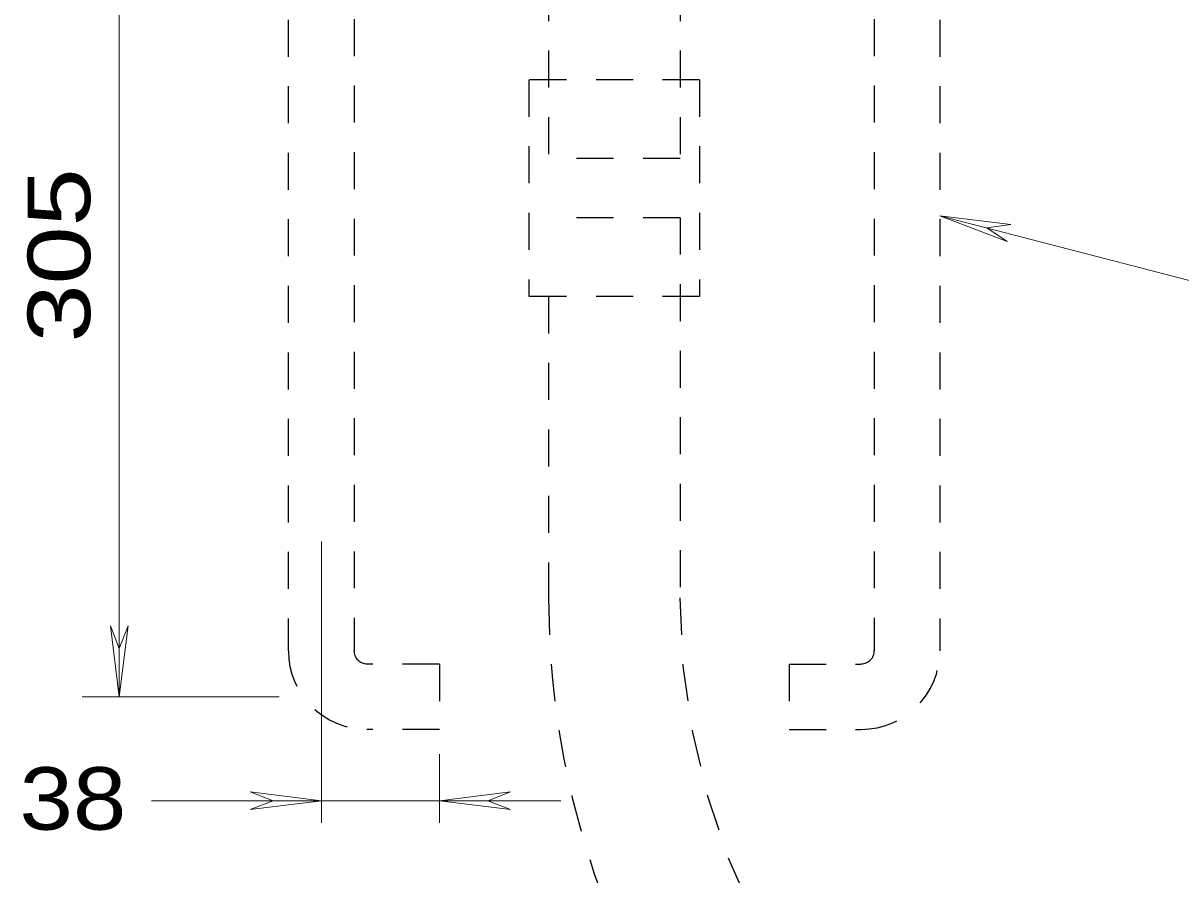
# Model space of a CAD drawing. Extents: x 312583 to 312854, y 144419 to 144597.
# Drawn here: x 312706.7 to 312720.79, y 144494.68 to 144505.05 of the extents above; entities that cross this region are included whole.
import ezdxf

# ---------------------------------------------------------------- set-up
doc = ezdxf.new("R2010")
doc.units = 0
doc.header["$LTSCALE"] = 0.3
doc.linetypes.add('SHORT_DASHED', pattern=[2.7, 1.5, -1.2])
doc.layers.add('1', color=7, linetype='Continuous', lineweight=25)
doc.layers.add('2', color=7, linetype='Continuous', lineweight=13)

msp = doc.modelspace()

# ---------------------------------------------------------------- linework, layer by layer
at = {"layer": '1', "linetype": 'SHORT_DASHED'}
for p, q in [((312713.0932, 144507.9535), (312713.0932, 144503.3995)), ((312714.6955, 144507.9535), (312714.6955, 144503.3995)), ((312709.9269, 144505.8989), (312709.9269, 144497.4042)), ((312710.7319, 144505.9065), (312710.7319, 144497.4042)), ((312717.0569, 144505.9065), (312717.0569, 144497.4042)), ((312717.8542, 144505.8989), (312717.8542, 144497.4042)), ((312714.9332, 144504.3579), (312712.8555, 144504.3579)), ((312712.8555, 144504.3579), (312712.8555, 144501.7205)), ((312714.9332, 144504.3579), (312714.9332, 144501.7205)), ((312714.6955, 144503.3995), (312713.0932, 144503.3995)), ((312714.6955, 144502.6789), (312713.0932, 144502.6789)), ((312714.6955, 144502.6789), (312714.6955, 144498.0482)), ((312714.9332, 144501.7205), (312712.8555, 144501.7205)), ((312713.0932, 144501.7205), (312713.0932, 144498.0482)), ((312711.7669, 144497.2432), (312710.8852, 144497.2432)), ((312711.7669, 144497.2432), (312711.7669, 144496.4459)), ((312716.0219, 144497.2432), (312716.0219, 144496.4459)), ((312716.0219, 144497.2432), (312716.8959, 144497.2432)), ((312711.7669, 144496.4459), (312710.8852, 144496.4459)), ((312716.0219, 144496.4459), (312716.8959, 144496.4459))]:
    msp.add_line(p, q, dxfattribs=at)
at = {"layer": '1', "lineweight": 13}
for p, q in [((312710.3332, 144498.7382), (312710.3332, 144495.3112)), ((312711.7669, 144496.1469), (312711.7669, 144495.3112)), ((312708.2632, 144495.5795), (312713.2465, 144495.5795))]:
    msp.add_line(p, q, dxfattribs=at)
at = {"layer": '1', "linetype": 'SHORT_DASHED'}
for centre, radius, start, end in [((312723.4767, 144498.0511), 10.3816, 180, 264.70346), ((312723.4767, 144498.0511), 8.785, 180, 263.73732), ((312710.8881, 144497.4071), 0.9583, 180, 270), ((312710.8881, 144497.4071), 0.16, 180, 270), ((312716.8987, 144497.4071), 0.9583, 270, 0), ((312716.8987, 144497.4071), 0.16, 270, 0)]:
    msp.add_arc(centre, radius, start, end, dxfattribs=at)
at = {"layer": '2'}
for p, q in [((312707.8722, 144496.8445), (312707.8722, 144507.3785)), ((312717.8542, 144502.7019), (312718.6745, 144502.3875)), ((312717.8542, 144502.7019), (312718.7205, 144502.5945)), ((312718.7205, 144502.5945), (312718.4292, 144502.5562)), ((312718.6745, 144502.3875), (312718.4292, 144502.5562)), ((312707.7649, 144497.7109), (312707.8722, 144497.4349)), ((312707.8722, 144496.8445), (312707.7649, 144497.7109)), ((312707.9795, 144497.7109), (312707.8722, 144497.4349)), ((312707.8722, 144496.8445), (312707.9795, 144497.7109)), ((312709.8195, 144496.8445), (312707.4199, 144496.8445)), ((312709.4669, 144495.6869), (312709.7429, 144495.5795)), ((312710.3332, 144495.5795), (312709.4669, 144495.6869)), ((312711.7669, 144495.5795), (312712.6332, 144495.6869)), ((312712.6332, 144495.6869), (312712.3572, 144495.5795)), ((312709.4669, 144495.4722), (312709.7429, 144495.5795)), ((312710.3332, 144495.5795), (312709.4669, 144495.4722)), ((312711.7669, 144495.5795), (312712.6332, 144495.4722)), ((312712.6332, 144495.4722), (312712.3572, 144495.5795))]:
    msp.add_line(p, q, dxfattribs=at)
msp.add_lwpolyline([(312723.9338, 144501.2529), (312723.4437, 144501.2529), (312717.8542, 144502.7019)], dxfattribs=at)

# ---------------------------------------------------------------- texts
at = {"layer": '2', "width": 1.25}
msp.add_text('305 ', height=0.76, rotation=90, dxfattribs=at).set_placement((312707.5177, 144501.1599))
at = {"layer": '2', "width": 1.15}
msp.add_text('38 ', height=0.76, dxfattribs=at).set_placement((312706.6584, 144495.2279))

doc.saveas('drawing.dxf')
